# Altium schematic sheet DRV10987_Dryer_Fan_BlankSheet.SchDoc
size 431 x 279 mm; Date: Not shown in title block; ApprovedBy: Not shown in title block; CheckedBy: Not shown in title block; Author: Not shown in title block; CompanyName: Not shown in title block; Engineer: Not shown in title block; Organization: Not shown in title block; Address1: Not shown in title block; Address2: Not shown in title block; Address3: Not shown in title block; Address4: Not shown in title block; DocumentNumber: 1; Revision: Use project parameter SCH_Rev; SheetNumber: 2; SheetTotal: 3; PageSetup: Record=PageOptions¦CenterHorizontal=True¦CenterVertical=True¦PrintScale=1.00¦XCorrection=1.00¦YCorrection=1.00¦PrintKind=0¦BorderSize=5000000¦LeftOffset=0¦BottomOffset=0¦Orientation=2¦PaperLength=1000¦PaperWidth=1000¦Scale=100¦PaperSource=15¦PrintQuality=600¦MediaType=1¦DitherType=10¦PaperKind=Letter¦PrintScaleMode=1
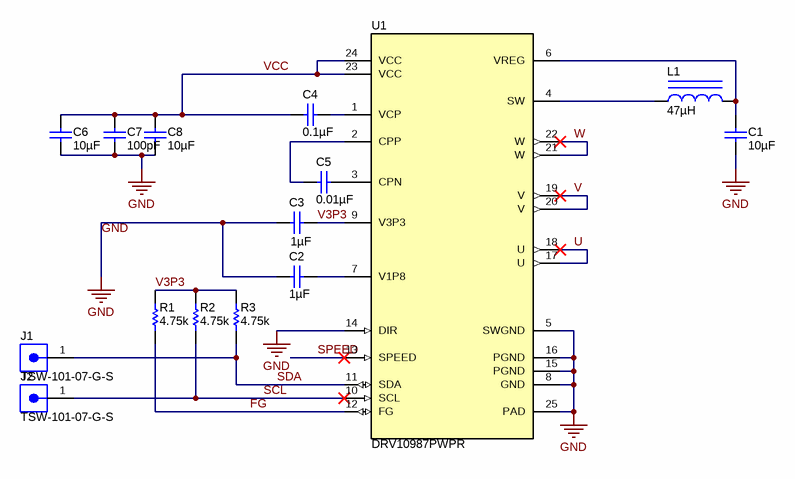
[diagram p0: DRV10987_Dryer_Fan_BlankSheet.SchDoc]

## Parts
C1  ValueDisplayed: 10µF  [0603L]  (hidden comment: C1608X6S1A106M080AC)
C2  ValueDisplayed: 1µF  [0603L]  (hidden comment: GRM185C80J105KE26D)
C3  ValueDisplayed: 1µF  [0603L]  (hidden comment: GRM185C80J105KE26D)
C4  ValueDisplayed: 0.1µF  [0603L]  (hidden comment: 06035C104KAT2A)
C5  ValueDisplayed: 0.01µF  [0603L]  (hidden comment: 0603ZC103KAT2A)
C6  ValueDisplayed: 10µF  [0603L]  (hidden comment: GRM188R6YA106MA73)
C7  ValueDisplayed: 100pF  [0603L]  (hidden comment: C0603C101J5GAC)
C8  ValueDisplayed: 10µF  [0805L]  (hidden comment: GRM21BR6YA106KE43L)
J1  TSW-101-07-G-S  [TSW-101-07-G-S]
J2  TSW-101-07-G-S  [TSW-101-07-G-S]
L1  ValueDisplayed: 47µH  [IND_CB2518]  (hidden comment: CB2518T470K)
R1  value 4.75k  [0603L]  (hidden comment: CRCW06034K75FKEA)
R2  value 4.75k  [0603L]  (hidden comment: CRCW06034K75FKEA)
R3  value 4.75k  [0603L]  (hidden comment: CRCW06034K75FKEA)
U1  DRV10987PWPR  [PWP0024B_N]

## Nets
GND: C1.2 C2.2 C3.2 C6.2 C7.1 C8.2 U1.5(SWGND) U1.8(GND) U1.14(DIR) U1.15(PGND) U1.16(PGND) U1.25(PAD)
FG: R1.2 U1.12(FG)
SCL: J2.1 R2.2 U1.10(SCL)
SDA: J1.1 R3.2 U1.11(SDA)
SPEED: U1.13(SPEED)
U: U1.17(U) U1.18(U)
V: U1.19(V) U1.20(V)
V3P3: C3.1 R1.1 R2.1 R3.1 U1.9(V3P3)
VCC: C4.2 C6.1 C7.2 C8.1 U1.23(VCC) U1.24(VCC)
W: U1.21(W) U1.22(W)
NetC1_1: C1.1 L1.2 U1.6(VREG)
NetC2_1: C2.1 U1.7(V1P8)
NetC4_1: C4.1 U1.1(VCP)
NetC5_1: C5.1 U1.3(CPN)
NetC5_2: C5.2 U1.2(CPP)
NetL1_1: L1.1 U1.4(SW)

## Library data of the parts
C1 = C1608X6S1A106M080AC: CAP, CERM, 10 µF, 10 V, +/- 10%, X6S, 0603; Manufacturer: TDK; Polarized: N; CompType: Capacitor; Value: 10uF; U/M: EA; Cap_F: 0.00001; Tolerance_%: 10; ESR_ohm: 0.004639; Value1: 0.004639 ohm; Value2: 10V; IRMS_A: 2.41407; TaMin_C: -55; TaMax_C: 105; Cap_Case: 0603; SizeArea_mm2: 1.28; SizeAreaWB_mm2: 4.68; SizeX_mm: 1.6; SizeY_mm: 0.8; SizeZ_mm: 1; AEC Category: Q200
C2 C3 = GRM185C80J105KE26D: CAP, CERM, 1 µF, 6.3 V, +/- 10%, X6S, 0603; Manufacturer: MuRata; Polarized: N; CompType: Capacitor; Value: 1uF; U/M: EA; Cap_F: 0.000001; Tolerance_%: 10; Value1: Unknown; VDC_V: 6.3; Value2: 6.3V; TaMin_C: -55; TaMax_C: 105; Cap_Case: 0603; SizeArea_mm2: 1.28; SizeAreaWB_mm2: 4.68; SizeX_mm: 1.6; SizeY_mm: 0.8; SizeZ_mm: 1; AEC Category: Q200; Green_Lifecycle: Active; Green_REACh: Passed
C4 = 06035C104KAT2A: CAP, CERM, 0.1uF, 50V, +/-10%, X7R, 0603; Manufacturer: AVX; Polarized: N; CompType: Capacitor; U/M: EA; Cap_F: 0.0000001; Tolerance_%: 10; Value1: Unknown; VDC_V: 50; TaMin_C: -55; TaMax_C: 125; Cap_Case: 0603
C5 = 0603ZC103KAT2A: CAP, CERM, 0.01 µF, 10 V, +/- 10%, X7R, 0603; Manufacturer: AVX; Polarized: N; CompType: Capacitor; Value: 0.01uF; U/M: EA; Cap_F: 0.00000001; Tolerance_%: 10; Value1: Unknown; Value2: 10V; TaMin_C: -55; TaMax_C: 125; Cap_Case: 0603; SizeArea_mm2: 1.28; SizeAreaWB_mm2: 4.68; SizeX_mm: 1.6; SizeY_mm: 0.8; SizeZ_mm: 1; AEC Category: Q200; Green_Lifecycle: Active; Green_REACh: Passed
C6 = GRM188R6YA106MA73: CAP, CERM, 10 µF, 35 V, +/- 20%, X5R, 0603; Manufacturer: Nichicon; Polarized: N; CompType: Capacitor; Value: 10uF; U/M: EA; Cap_F: 0.00001; Tolerance_%: 20; Value1: Unknown; VDC_V: 35; Value2: 35V; TaMin_C: -55; TaMax_C: 85; Cap_Case: 0603; SizeArea_mm2: 1.28; SizeAreaWB_mm2: 4.68; SizeX_mm: 1.6; SizeY_mm: 0.8; SizeZ_mm: 1; AEC Category: Q200
C7 = C0603C101J5GAC: CAP, CERM, 100 pF, 50 V, +/- 5%, C0G/NP0, 0603; Manufacturer: Kemet; Polarized: N; CompType: Capacitor; Value: 100pF; U/M: EA; Cap_F: 0.0000000001; Tolerance_%: 5; Value1: Unknown; VDC_V: 50; Value2: 50V; TaMin_C: -55; TaMax_C: 125; Cap_Case: 0603; SizeArea_mm2: 1.28; SizeAreaWB_mm2: 4.68; SizeX_mm: 1.6; SizeY_mm: 0.8; SizeZ_mm: 1; AEC Category: Q200; Green_Lifecycle: Active; Green_REACh: Passed
C8 = GRM21BR6YA106KE43L: CAP, CERM, 10 µF, 35 V, +/- 10%, X5R, 0805; Manufacturer: MuRata; Polarized: N; CompType: Capacitor; Value: 10uF; U/M: EA; Cap_F: 0.00001; Tolerance_%: 10; Value1: Unknown; VDC_V: 35; Value2: 35V; TaMin_C: -55; TaMax_C: 85; Cap_Case: 0805; SizeArea_mm2: 2.5; SizeAreaWB_mm2: 6.75; SizeX_mm: 2; SizeY_mm: 1.25; SizeZ_mm: 1.45; AEC Category: Q200; Green_Lifecycle: Active; Green_REACh: Passed
J1 J2 = TSW-101-07-G-S: Header, 100mil, 1pos, Gold, TH; Manufacturer: Samtec; SymbolCreator: a0412235; Pitch_mm: 2.54; Gender: Male; Shrouded: N; Row_Count: 1; Current_A: 6.3; Voltage_V: 550; Cert_CSA: Y
L1 = CB2518T470K: Inductor, Wirewound, Ferrite, 47 µH, 0.11 A, 1.235 ohm, SMD; Manufacturer: Taiyo Yuden; Value: 47uH; Ind_H: 47.0E-6; Imax_A: 0.11; Irms: 0.42A @ 40C rise; Isat: 0.11A @ 30% inductance drop; DCR_ohm: 1.235; Value2: 0.11A; SizeAreaWB_mm2: 9.8; SizeArea_mm2: 4.5; SizeX_mm: 2.5; SizeY_mm: 1.8; SizeZ_mm: 2; AEC Category: Q200; Green_Lifecycle: Active; Green_REACh: Passed
R1-R3 = CRCW06034K75FKEA: RES, 4.75k ohm, 1%, 0.1W, 0603; Manufacturer: Vishay-Dale; CompType: Resistor; Res_ohm: 4750; Value_Code: 4k75; Tolerance_%: 1; Power_W: 0.1; VDC_V: 75; TempCo: 100 ppm/C; EIA_Code: E96; U/M: EA
U1 = DRV10987PWPR: 12- to 24-V, Three-Phase, Sensorless BLDC Motor Driver, PWP0024B (TSSOP-24); Manufacturer: Texas Instruments; SymbolCreator: a0411947; SizeArea_mm2: 49.92; SizeAreaWB_mm2: 82.32; SizeX_mm: 6.4; SizeY_mm: 7.8; SizeZ_mm: 1.2; CompType: IC; U/M: EA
